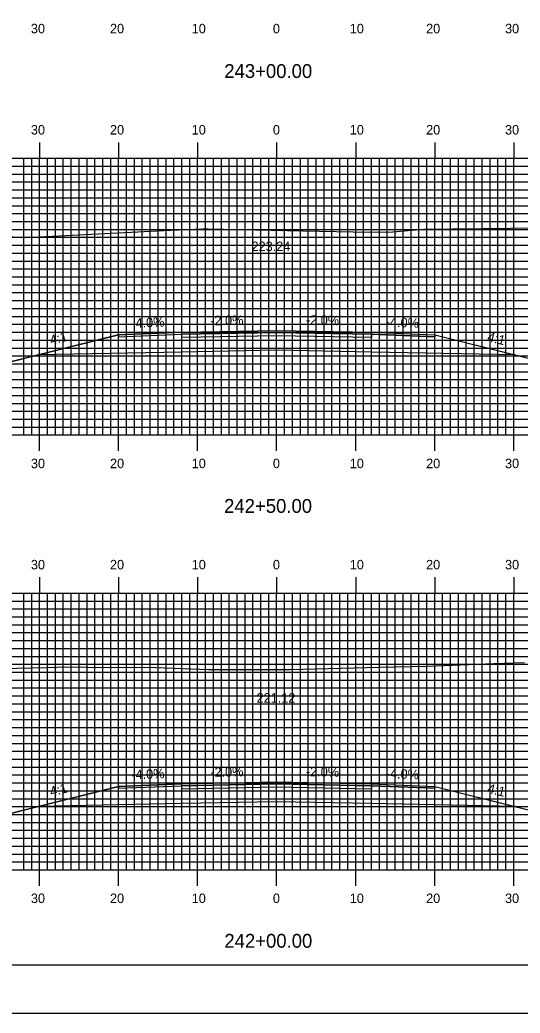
# Model space of a CAD drawing. Extents: x 1802323 to 1802666, y 442591 to 442811.
# Drawn here: x 1802456.1 to 1802519.4, y 442590.5 to 442716.2 of the extents above; entities that cross this region are included whole.
import ezdxf

# ---------------------------------------------------------------- set-up
doc = ezdxf.new("R2010")
doc.units = 0
for name, color, linetype in [('ANNOTATION', 7, 'Continuous'), ('BORDER', 7, 'Continuous'), ('D_Roadway_Centerline', 7, 'Continuous'), ('D_Roadway_Centerline_Text', 7, 'Continuous'), ('D_Roadway_Edge_Shoulder', 7, 'Continuous'), ('D_Roadway_Edge_TW', 7, 'Continuous'), ('D_Roadway_Pavement', 7, 'Continuous'), ('D_Roadway_SlopeLines', 7, 'Continuous'), ('D_Roadway_SubGrade', 7, 'Continuous'), ('H_V ANNOTATION', 7, 'Continuous'), ('MAJOR', 7, 'Continuous'), ('MINOR', 7, 'Continuous'), ('PLOT BOUNDARY', 7, 'Continuous'), ('S_Roadway_Centerline', 7, 'Continuous')]:
    doc.layers.add(name, color=color, linetype=linetype)

msp = doc.modelspace()

# ---------------------------------------------------------------- linework, layer by layer
at = {"layer": 'BORDER'}
msp.add_lwpolyline([(1802339, 442596.67), (1802659, 442596.67), (1802659, 442806.67), (1802339, 442806.67)], close=True, dxfattribs=at)
at = {"layer": 'D_Roadway_Centerline'}
for points in [[(1802396.07, 442689.17), (1802397.32, 442689.09), (1802398.57, 442688.93), (1802399.82, 442688.68), (1802401.07, 442688.36), (1802454.43, 442672.8), (1802458.43, 442673.8), (1802468.6, 442676.34), (1802476.6, 442676.66), (1802488.6, 442676.9), (1802500.6, 442676.66), (1802508.6, 442676.34), (1802518.78, 442673.8), (1802522.78, 442672.8), (1802578.12, 442688.94), (1802579.37, 442689.26), (1802580.62, 442689.49), (1802581.87, 442689.62), (1802583.12, 442689.67)], [(1802397.15, 442633.97), (1802398.4, 442633.91), (1802399.65, 442633.74), (1802400.9, 442633.48), (1802402.15, 442633.11), (1802454.43, 442615.69), (1802458.43, 442616.69), (1802468.6, 442619.23), (1802476.6, 442619.55), (1802488.6, 442619.79), (1802500.6, 442619.55), (1802508.6, 442619.23), (1802518.78, 442616.69), (1802522.78, 442615.69), (1802577.02, 442633.77), (1802578.27, 442634.13), (1802579.52, 442634.39), (1802580.77, 442634.56), (1802582.02, 442634.61)]]:
    msp.add_lwpolyline(points, dxfattribs=at)
at = {"layer": 'D_Roadway_Edge_Shoulder'}
for points in [[(1802476.6, 442676.66), (1802468.6, 442676.34), (1802468.6, 442676.09), (1802476.6, 442676.41)], [(1802500.6, 442676.66), (1802508.6, 442676.34), (1802508.6, 442676.09), (1802500.6, 442676.41)], [(1802476.6, 442619.55), (1802468.6, 442619.23), (1802468.6, 442618.98), (1802476.6, 442619.3)], [(1802500.6, 442619.55), (1802508.6, 442619.23), (1802508.6, 442618.98), (1802500.6, 442619.3)]]:
    msp.add_lwpolyline(points, close=True, dxfattribs=at)
at = {"layer": 'D_Roadway_Edge_TW'}
for points in [[(1802476.6, 442676.41), (1802476.6, 442676.66), (1802488.6, 442676.9), (1802500.6, 442676.66), (1802500.6, 442676.41), (1802488.6, 442676.65)], [(1802476.6, 442619.3), (1802476.6, 442619.55), (1802488.6, 442619.79), (1802500.6, 442619.55), (1802500.6, 442619.3), (1802488.6, 442619.54)]]:
    msp.add_lwpolyline(points, close=True, dxfattribs=at)
at = {"layer": 'D_Roadway_Pavement'}
for points in [[(1802476.6, 442675.99), (1802476.6, 442676.41), (1802488.6, 442676.65), (1802500.6, 442676.41), (1802500.6, 442675.99), (1802488.6, 442676.23)], [(1802476.6, 442618.88), (1802476.6, 442619.3), (1802488.6, 442619.54), (1802500.6, 442619.3), (1802500.6, 442618.88), (1802488.6, 442619.12)]]:
    msp.add_lwpolyline(points, close=True, dxfattribs=at)
at = {"layer": 'D_Roadway_SlopeLines'}
for points in [[(1802468.6, 442676.34), (1802454.43, 442672.8)], [(1802508.6, 442676.34), (1802522.78, 442672.8)], [(1802468.6, 442619.23), (1802454.43, 442615.69)], [(1802508.6, 442619.23), (1802522.78, 442615.69)]]:
    msp.add_lwpolyline(points, dxfattribs=at)
at = {"layer": 'D_Roadway_SubGrade'}
for points in [[(1802476.6, 442674.16), (1802458.43, 442673.8), (1802468.6, 442676.34), (1802468.6, 442676.09), (1802476.6, 442676.41), (1802488.6, 442676.65), (1802500.6, 442676.41), (1802508.6, 442676.09), (1802508.6, 442676.34), (1802518.78, 442673.8), (1802500.6, 442674.16), (1802488.6, 442674.4)], [(1802476.6, 442617.05), (1802458.43, 442616.69), (1802468.6, 442619.23), (1802468.6, 442618.98), (1802476.6, 442619.3), (1802488.6, 442619.54), (1802500.6, 442619.3), (1802508.6, 442618.98), (1802508.6, 442619.23), (1802518.78, 442616.69), (1802500.6, 442617.05), (1802488.6, 442617.29)]]:
    msp.add_lwpolyline(points, close=True, dxfattribs=at)
at = {"layer": 'MAJOR'}
for p, q in [((1802458.6, 442700.67), (1802458.6, 442698.67)), ((1802468.6, 442700.67), (1802468.6, 442698.67)), ((1802478.6, 442700.67), (1802478.6, 442698.67)), ((1802488.6, 442700.67), (1802488.6, 442698.67)), ((1802498.6, 442700.67), (1802498.6, 442698.67)), ((1802508.6, 442700.67), (1802508.6, 442698.67)), ((1802518.6, 442700.67), (1802518.6, 442698.67)), ((1802348.6, 442698.67), (1802628.6, 442698.67)), ((1802348.6, 442698.67), (1802628.6, 442698.67)), ((1802458.6, 442663.67), (1802458.6, 442698.67)), ((1802468.6, 442663.67), (1802468.6, 442698.67)), ((1802478.6, 442663.67), (1802478.6, 442698.67)), ((1802488.6, 442663.67), (1802488.6, 442698.67)), ((1802498.6, 442663.67), (1802498.6, 442698.67)), ((1802508.6, 442663.67), (1802508.6, 442698.67)), ((1802518.6, 442663.67), (1802518.6, 442698.67)), ((1802348.6, 442693.67), (1802628.6, 442693.67)), ((1802348.6, 442688.67), (1802628.6, 442688.67)), ((1802348.6, 442683.67), (1802628.6, 442683.67)), ((1802348.6, 442678.67), (1802628.6, 442678.67)), ((1802348.6, 442673.67), (1802628.6, 442673.67)), ((1802348.6, 442668.67), (1802628.6, 442668.67)), ((1802348.6, 442663.67), (1802628.6, 442663.67)), ((1802348.6, 442663.67), (1802628.6, 442663.67)), ((1802458.6, 442661.66), (1802458.6, 442663.67)), ((1802468.6, 442661.66), (1802468.6, 442663.67)), ((1802478.6, 442661.66), (1802478.6, 442663.67)), ((1802488.6, 442661.66), (1802488.6, 442663.67)), ((1802498.6, 442661.66), (1802498.6, 442663.67)), ((1802508.6, 442661.66), (1802508.6, 442663.67)), ((1802518.6, 442661.66), (1802518.6, 442663.67)), ((1802458.6, 442645.67), (1802458.6, 442643.67)), ((1802468.6, 442645.67), (1802468.6, 442643.67)), ((1802478.6, 442645.67), (1802478.6, 442643.67)), ((1802488.6, 442645.67), (1802488.6, 442643.67)), ((1802498.6, 442645.67), (1802498.6, 442643.67)), ((1802508.6, 442645.67), (1802508.6, 442643.67)), ((1802518.6, 442645.67), (1802518.6, 442643.67)), ((1802348.6, 442643.67), (1802628.6, 442643.67)), ((1802348.6, 442643.67), (1802628.6, 442643.67)), ((1802458.6, 442608.67), (1802458.6, 442643.67)), ((1802468.6, 442608.67), (1802468.6, 442643.67)), ((1802478.6, 442608.67), (1802478.6, 442643.67)), ((1802488.6, 442608.67), (1802488.6, 442643.67)), ((1802498.6, 442608.67), (1802498.6, 442643.67)), ((1802508.6, 442608.67), (1802508.6, 442643.67)), ((1802518.6, 442608.67), (1802518.6, 442643.67)), ((1802348.6, 442638.67), (1802628.6, 442638.67)), ((1802348.6, 442633.67), (1802628.6, 442633.67)), ((1802348.6, 442628.67), (1802628.6, 442628.67)), ((1802348.6, 442623.67), (1802628.6, 442623.67)), ((1802348.6, 442618.67), (1802628.6, 442618.67)), ((1802348.6, 442613.67), (1802628.6, 442613.67)), ((1802348.6, 442608.67), (1802628.6, 442608.67)), ((1802348.6, 442608.67), (1802628.6, 442608.67)), ((1802458.6, 442606.66), (1802458.6, 442608.67)), ((1802468.6, 442606.66), (1802468.6, 442608.67)), ((1802478.6, 442606.66), (1802478.6, 442608.67)), ((1802488.6, 442606.66), (1802488.6, 442608.67)), ((1802498.6, 442606.66), (1802498.6, 442608.67)), ((1802508.6, 442606.66), (1802508.6, 442608.67)), ((1802518.6, 442606.66), (1802518.6, 442608.67))]:
    msp.add_line(p, q, dxfattribs=at)
at = {"layer": 'MINOR'}
for p, q in [((1802456.6, 442663.67), (1802456.6, 442698.67)), ((1802457.6, 442663.67), (1802457.6, 442698.67)), ((1802459.6, 442663.67), (1802459.6, 442698.67)), ((1802460.6, 442663.67), (1802460.6, 442698.67)), ((1802461.6, 442663.67), (1802461.6, 442698.67)), ((1802462.6, 442663.67), (1802462.6, 442698.67)), ((1802463.6, 442663.67), (1802463.6, 442698.67)), ((1802464.6, 442663.67), (1802464.6, 442698.67)), ((1802465.6, 442663.67), (1802465.6, 442698.67)), ((1802466.6, 442663.67), (1802466.6, 442698.67)), ((1802467.6, 442663.67), (1802467.6, 442698.67)), ((1802469.6, 442663.67), (1802469.6, 442698.67)), ((1802470.6, 442663.67), (1802470.6, 442698.67)), ((1802471.6, 442663.67), (1802471.6, 442698.67)), ((1802472.6, 442663.67), (1802472.6, 442698.67)), ((1802473.6, 442663.67), (1802473.6, 442698.67)), ((1802474.6, 442663.67), (1802474.6, 442698.67)), ((1802475.6, 442663.67), (1802475.6, 442698.67)), ((1802476.6, 442663.67), (1802476.6, 442698.67)), ((1802477.6, 442663.67), (1802477.6, 442698.67)), ((1802479.6, 442663.67), (1802479.6, 442698.67)), ((1802480.6, 442663.67), (1802480.6, 442698.67)), ((1802481.6, 442663.67), (1802481.6, 442698.67)), ((1802482.6, 442663.67), (1802482.6, 442698.67)), ((1802483.6, 442663.67), (1802483.6, 442698.67)), ((1802484.6, 442663.67), (1802484.6, 442698.67)), ((1802485.6, 442663.67), (1802485.6, 442698.67)), ((1802486.6, 442663.67), (1802486.6, 442698.67)), ((1802487.6, 442663.67), (1802487.6, 442698.67)), ((1802489.6, 442663.67), (1802489.6, 442698.67)), ((1802490.6, 442663.67), (1802490.6, 442698.67)), ((1802491.6, 442663.67), (1802491.6, 442698.67)), ((1802492.6, 442663.67), (1802492.6, 442698.67)), ((1802493.6, 442663.67), (1802493.6, 442698.67)), ((1802494.6, 442663.67), (1802494.6, 442698.67)), ((1802495.6, 442663.67), (1802495.6, 442698.67)), ((1802496.6, 442663.67), (1802496.6, 442698.67)), ((1802497.6, 442663.67), (1802497.6, 442698.67)), ((1802499.6, 442663.67), (1802499.6, 442698.67)), ((1802500.6, 442663.67), (1802500.6, 442698.67)), ((1802501.6, 442663.67), (1802501.6, 442698.67)), ((1802502.6, 442663.67), (1802502.6, 442698.67)), ((1802503.6, 442663.67), (1802503.6, 442698.67)), ((1802504.6, 442663.67), (1802504.6, 442698.67)), ((1802505.6, 442663.67), (1802505.6, 442698.67)), ((1802506.6, 442663.67), (1802506.6, 442698.67)), ((1802507.6, 442663.67), (1802507.6, 442698.67)), ((1802509.6, 442663.67), (1802509.6, 442698.67)), ((1802510.6, 442663.67), (1802510.6, 442698.67)), ((1802511.6, 442663.67), (1802511.6, 442698.67)), ((1802512.6, 442663.67), (1802512.6, 442698.67)), ((1802513.6, 442663.67), (1802513.6, 442698.67)), ((1802514.6, 442663.67), (1802514.6, 442698.67)), ((1802515.6, 442663.67), (1802515.6, 442698.67)), ((1802516.6, 442663.67), (1802516.6, 442698.67)), ((1802517.6, 442663.67), (1802517.6, 442698.67)), ((1802348.6, 442697.67), (1802628.6, 442697.67)), ((1802348.6, 442696.67), (1802628.6, 442696.67)), ((1802348.6, 442695.67), (1802628.6, 442695.67)), ((1802348.6, 442694.67), (1802628.6, 442694.67)), ((1802348.6, 442692.67), (1802628.6, 442692.67)), ((1802348.6, 442691.67), (1802628.6, 442691.67)), ((1802348.6, 442690.67), (1802628.6, 442690.67)), ((1802348.6, 442689.67), (1802628.6, 442689.67)), ((1802348.6, 442687.67), (1802628.6, 442687.67)), ((1802348.6, 442686.67), (1802628.6, 442686.67)), ((1802348.6, 442685.67), (1802628.6, 442685.67)), ((1802348.6, 442684.67), (1802628.6, 442684.67)), ((1802348.6, 442682.67), (1802628.6, 442682.67)), ((1802348.6, 442681.67), (1802628.6, 442681.67)), ((1802348.6, 442680.67), (1802628.6, 442680.67)), ((1802348.6, 442679.67), (1802628.6, 442679.67)), ((1802348.6, 442677.67), (1802628.6, 442677.67)), ((1802348.6, 442676.67), (1802628.6, 442676.67)), ((1802348.6, 442675.67), (1802628.6, 442675.67)), ((1802348.6, 442674.67), (1802628.6, 442674.67)), ((1802348.6, 442672.67), (1802628.6, 442672.67)), ((1802348.6, 442671.67), (1802628.6, 442671.67)), ((1802348.6, 442670.67), (1802628.6, 442670.67)), ((1802348.6, 442669.67), (1802628.6, 442669.67)), ((1802348.6, 442667.67), (1802628.6, 442667.67)), ((1802348.6, 442666.67), (1802628.6, 442666.67)), ((1802348.6, 442665.67), (1802628.6, 442665.67)), ((1802348.6, 442664.67), (1802628.6, 442664.67)), ((1802456.6, 442608.67), (1802456.6, 442643.67)), ((1802457.6, 442608.67), (1802457.6, 442643.67)), ((1802459.6, 442608.67), (1802459.6, 442643.67)), ((1802460.6, 442608.67), (1802460.6, 442643.67)), ((1802461.6, 442608.67), (1802461.6, 442643.67)), ((1802462.6, 442608.67), (1802462.6, 442643.67)), ((1802463.6, 442608.67), (1802463.6, 442643.67)), ((1802464.6, 442608.67), (1802464.6, 442643.67)), ((1802465.6, 442608.67), (1802465.6, 442643.67)), ((1802466.6, 442608.67), (1802466.6, 442643.67)), ((1802467.6, 442608.67), (1802467.6, 442643.67)), ((1802469.6, 442608.67), (1802469.6, 442643.67)), ((1802470.6, 442608.67), (1802470.6, 442643.67)), ((1802471.6, 442608.67), (1802471.6, 442643.67)), ((1802472.6, 442608.67), (1802472.6, 442643.67)), ((1802473.6, 442608.67), (1802473.6, 442643.67)), ((1802474.6, 442608.67), (1802474.6, 442643.67)), ((1802475.6, 442608.67), (1802475.6, 442643.67)), ((1802476.6, 442608.67), (1802476.6, 442643.67)), ((1802477.6, 442608.67), (1802477.6, 442643.67)), ((1802479.6, 442608.67), (1802479.6, 442643.67)), ((1802480.6, 442608.67), (1802480.6, 442643.67)), ((1802481.6, 442608.67), (1802481.6, 442643.67)), ((1802482.6, 442608.67), (1802482.6, 442643.67)), ((1802483.6, 442608.67), (1802483.6, 442643.67)), ((1802484.6, 442608.67), (1802484.6, 442643.67)), ((1802485.6, 442608.67), (1802485.6, 442643.67)), ((1802486.6, 442608.67), (1802486.6, 442643.67)), ((1802487.6, 442608.67), (1802487.6, 442643.67)), ((1802489.6, 442608.67), (1802489.6, 442643.67)), ((1802490.6, 442608.67), (1802490.6, 442643.67)), ((1802491.6, 442608.67), (1802491.6, 442643.67)), ((1802492.6, 442608.67), (1802492.6, 442643.67)), ((1802493.6, 442608.67), (1802493.6, 442643.67)), ((1802494.6, 442608.67), (1802494.6, 442643.67)), ((1802495.6, 442608.67), (1802495.6, 442643.67)), ((1802496.6, 442608.67), (1802496.6, 442643.67)), ((1802497.6, 442608.67), (1802497.6, 442643.67)), ((1802499.6, 442608.67), (1802499.6, 442643.67)), ((1802500.6, 442608.67), (1802500.6, 442643.67)), ((1802501.6, 442608.67), (1802501.6, 442643.67)), ((1802502.6, 442608.67), (1802502.6, 442643.67)), ((1802503.6, 442608.67), (1802503.6, 442643.67)), ((1802504.6, 442608.67), (1802504.6, 442643.67)), ((1802505.6, 442608.67), (1802505.6, 442643.67)), ((1802506.6, 442608.67), (1802506.6, 442643.67)), ((1802507.6, 442608.67), (1802507.6, 442643.67)), ((1802509.6, 442608.67), (1802509.6, 442643.67)), ((1802510.6, 442608.67), (1802510.6, 442643.67)), ((1802511.6, 442608.67), (1802511.6, 442643.67)), ((1802512.6, 442608.67), (1802512.6, 442643.67)), ((1802513.6, 442608.67), (1802513.6, 442643.67)), ((1802514.6, 442608.67), (1802514.6, 442643.67)), ((1802515.6, 442608.67), (1802515.6, 442643.67)), ((1802516.6, 442608.67), (1802516.6, 442643.67)), ((1802517.6, 442608.67), (1802517.6, 442643.67)), ((1802348.6, 442642.67), (1802628.6, 442642.67)), ((1802348.6, 442641.67), (1802628.6, 442641.67)), ((1802348.6, 442640.67), (1802628.6, 442640.67)), ((1802348.6, 442639.67), (1802628.6, 442639.67)), ((1802348.6, 442637.67), (1802628.6, 442637.67)), ((1802348.6, 442636.67), (1802628.6, 442636.67)), ((1802348.6, 442635.67), (1802628.6, 442635.67)), ((1802348.6, 442634.67), (1802628.6, 442634.67)), ((1802348.6, 442632.67), (1802628.6, 442632.67)), ((1802348.6, 442631.67), (1802628.6, 442631.67)), ((1802348.6, 442630.67), (1802628.6, 442630.67)), ((1802348.6, 442629.67), (1802628.6, 442629.67)), ((1802348.6, 442627.67), (1802628.6, 442627.67)), ((1802348.6, 442626.67), (1802628.6, 442626.67)), ((1802348.6, 442625.67), (1802628.6, 442625.67)), ((1802348.6, 442624.67), (1802628.6, 442624.67)), ((1802348.6, 442622.67), (1802628.6, 442622.67)), ((1802348.6, 442621.67), (1802628.6, 442621.67)), ((1802348.6, 442620.67), (1802628.6, 442620.67)), ((1802348.6, 442619.67), (1802628.6, 442619.67)), ((1802348.6, 442617.67), (1802628.6, 442617.67)), ((1802348.6, 442616.67), (1802628.6, 442616.67)), ((1802348.6, 442615.67), (1802628.6, 442615.67)), ((1802348.6, 442614.67), (1802628.6, 442614.67)), ((1802348.6, 442612.67), (1802628.6, 442612.67)), ((1802348.6, 442611.67), (1802628.6, 442611.67)), ((1802348.6, 442610.67), (1802628.6, 442610.67)), ((1802348.6, 442609.67), (1802628.6, 442609.67))]:
    msp.add_line(p, q, dxfattribs=at)
at = {"layer": 'PLOT BOUNDARY'}
msp.add_lwpolyline([(1802322.81, 442590.55), (1802662.81, 442590.55), (1802662.81, 442810.55), (1802322.81, 442810.55)], close=True, dxfattribs=at)
at = {"layer": 'S_Roadway_Centerline'}
for points in [[(1802386.15, 442689.57), (1802393.97, 442689.24), (1802398.55, 442689.09), (1802403.98, 442689.02), (1802415.14, 442688.89), (1802421.74, 442688.91), (1802429.72, 442688.89), (1802436.44, 442688.95), (1802455.25, 442688.74), (1802457.75, 442688.7), (1802475.15, 442689.57), (1802479.26, 442689.76), (1802479.55, 442689.78), (1802479.89, 442689.76), (1802491.93, 442689.49), (1802500.39, 442689.33), (1802503.32, 442689.37), (1802507.23, 442689.68), (1802521.77, 442689.85)], [(1802386.95, 442634.08), (1802395.18, 442633.99), (1802403.07, 442633.91), (1802414.26, 442633.85), (1802415.51, 442633.82), (1802416.43, 442633.81), (1802427.25, 442633.83), (1802437.24, 442633.81), (1802439.05, 442633.85), (1802449.8, 442634.07), (1802459.65, 442634.28), (1802461.93, 442634.36), (1802464.62, 442634.32), (1802473.33, 442634.27), (1802479.98, 442634.01), (1802490.3, 442634), (1802501.57, 442634.31), (1802507.7, 442634.41), (1802516.07, 442634.75), (1802519.95, 442634.88)]]:
    msp.add_lwpolyline(points, dxfattribs=at)

# ---------------------------------------------------------------- texts
at = {"layer": 'ANNOTATION'}
for s, rotation, p in [('-4.0%', 2.2906, (1802470.23, 442677.21)), ('-2.0%', 1.1458, (1802480.21, 442677.53)), ('-2.0%', 358.8542, (1802492.29, 442677.63)), ('-4.0%', 357.7094, (1802502.39, 442677.39)), ('4:1', 14.0362, (1802460.05, 442675.06)), ('4:1', 345.9638, (1802515.19, 442675.55)), ('-2.0%', 1.1458, (1802480.21, 442620.42)), ('-2.0%', 358.8542, (1802492.29, 442620.52)), ('-4.0%', 2.2906, (1802470.23, 442620.1)), ('-4.0%', 357.7094, (1802502.39, 442620.28)), ('4:1', 14.0362, (1802460.05, 442617.95)), ('4:1', 345.9638, (1802515.19, 442618.44))]:
    msp.add_text(s, height=1.2, rotation=rotation, dxfattribs=at).set_placement(p)
at = {"layer": 'D_Roadway_Centerline'}
for s, p in [('C', (1802488.6, 442676.9)), ('L', (1802488.6, 442676.89)), ('C', (1802488.6, 442619.79)), ('L', (1802488.6, 442619.78))]:
    msp.add_text(s, height=0.0146, dxfattribs=at).set_placement(p)
at = {"layer": 'D_Roadway_Centerline_Text'}
for s, p in [('223.24', (1802485.42, 442686.93)), ('221.12', (1802486.06, 442629.82))]:
    msp.add_text(s, height=1.2, dxfattribs=at).set_placement(p)
at = {"layer": 'H_V ANNOTATION'}
for s, height, p in [('30', 1.2, (1802457.5, 442714.47)), ('20', 1.2, (1802467.51, 442714.47)), ('10', 1.2, (1802477.85, 442714.47)), ('0', 1.2, (1802488.12, 442714.47)), ('10', 1.2, (1802497.85, 442714.47)), ('20', 1.2, (1802507.51, 442714.47)), ('30', 1.2, (1802517.5, 442714.47)), ('243+00.00', 1.75, (1802481.97, 442708.82)), ('30', 1.2, (1802457.5, 442701.67)), ('20', 1.2, (1802467.51, 442701.67)), ('10', 1.2, (1802477.85, 442701.67)), ('0', 1.2, (1802488.12, 442701.67)), ('10', 1.2, (1802497.85, 442701.67)), ('20', 1.2, (1802507.51, 442701.67)), ('30', 1.2, (1802517.5, 442701.67)), ('30', 1.2, (1802457.5, 442659.47)), ('20', 1.2, (1802467.51, 442659.47)), ('10', 1.2, (1802477.85, 442659.47)), ('0', 1.2, (1802488.12, 442659.47)), ('10', 1.2, (1802497.85, 442659.47)), ('20', 1.2, (1802507.51, 442659.47)), ('30', 1.2, (1802517.5, 442659.47)), ('242+50.00', 1.75, (1802481.95, 442653.82)), ('30', 1.2, (1802457.5, 442646.67)), ('20', 1.2, (1802467.51, 442646.67)), ('10', 1.2, (1802477.85, 442646.67)), ('0', 1.2, (1802488.12, 442646.67)), ('10', 1.2, (1802497.85, 442646.67)), ('20', 1.2, (1802507.51, 442646.67)), ('30', 1.2, (1802517.5, 442646.67)), ('30', 1.2, (1802457.5, 442604.47)), ('20', 1.2, (1802467.51, 442604.47)), ('10', 1.2, (1802477.85, 442604.47)), ('0', 1.2, (1802488.12, 442604.47)), ('10', 1.2, (1802497.85, 442604.47)), ('20', 1.2, (1802507.51, 442604.47)), ('30', 1.2, (1802517.5, 442604.47)), ('242+00.00', 1.75, (1802481.98, 442598.82))]:
    msp.add_text(s, height=height, dxfattribs=at).set_placement(p)

doc.saveas('drawing.dxf')
